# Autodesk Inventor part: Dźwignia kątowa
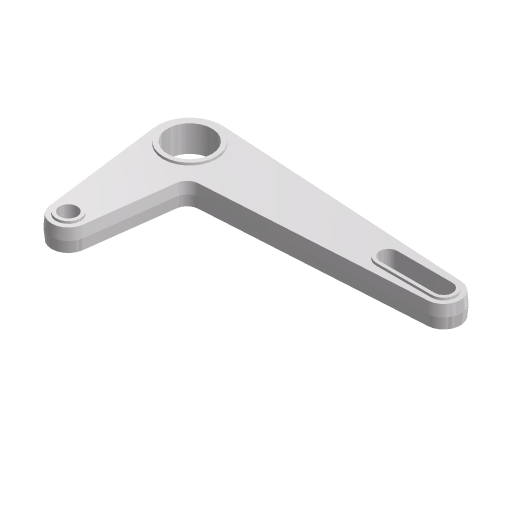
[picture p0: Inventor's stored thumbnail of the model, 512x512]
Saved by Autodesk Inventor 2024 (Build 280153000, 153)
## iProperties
Company: ATC
Shininess: 20.0
Angle Display Precision: 2
Document Length Units: 11269
Document Angle Units: 11279
Document Time Units: 11290
Document Mass Units: 11283
Document Length Units Precision: 3
Document Angle Units Precision: 2
Created: 2023-03
Part Number: Dźwignia kątowa
Material: Kurs-AJ
Document SubType Name: Modelowanie
Designer: Andrzej Jaskulski
Density: 1 g/cm^3
Stock Number: Dźwignia kątowa
Mass: 346.136 g
Surface Area: 128.086 cm^2
Volume: 34.6136 cm^3
Appearance: Kurs-AJ
Checked By: A.J.
Engr Approved By: Andrzej Jaskulski
Mfg Approved By: Andrzej Jaskulski
Authority: A.J.
Density: 0.0
Volumn: 0.0
Area: 0.0
PropertySet Name: Model Information
Control State: 0
Master: False
Checked Out: False
Title: A.J.: Kurs R2024-MEP
Author: Andrzej Jaskulski
Revision Number: 1/24
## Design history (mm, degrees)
node "Bryła1"
node "Korpusy bryłowe"
node "Korpusy powierzchniowe"
node "Początek"
sketch "Szkic1"
  geometry: L1 (-25.035, -9.169)-(89.965, -9.169); L2 (-24.122, 5.803)-(90.452, -1.184); L3 (90.452, -17.155)-(-7.608, -23.135); L4 (-25.035, -9.169)-(-25.035, -66.201); L5 (-39.913, -11.079)-(-32.97, -65.188); L6 (-17.1, -65.188)-(-12.263, -27.489); L7 (64.965, -5.169)-(89.965, -5.169); L8 (89.965, -13.169)-(64.965, -13.169); L9 (89.965, -3.169)-(64.965, -3.169); L10 (64.965, -15.169)-(89.965, -15.169); C1 r 12.5 at (-25.035, -9.169); C2 r 6 at (-25.035, -64.169); C3 r 4 at (-25.035, -64.169); C4 r 10 at (-25.035, -9.169); A1 r 8 centre (89.965, -9.169) between (90.452, -17.155) and (90.452, -1.184); A2 r 8 centre (-25.035, -64.169) between (-32.97, -65.188) and (-17.1, -65.188); A3 r 4 centre (64.965, -9.169) between (64.965, -5.169) and (64.965, -13.169); A4 r 4 centre (89.965, -9.169) between (89.965, -13.169) and (89.965, -5.169); A5 r 113.425 centre (-25.035, -9.169) between (67.111, -75.309) and (85.385, 16.766); A6 r 5 centre (-7.304, -28.125) between (-7.608, -23.135) and (-12.263, -27.489); A7 r 15 centre (-25.035, -9.169) between (-24.122, 5.803) and (-39.913, -11.079); A8 r 6 centre (64.965, -9.169) between (64.965, -3.169) and (64.965, -15.169); A9 r 6 centre (89.965, -9.169) between (89.965, -15.169) and (89.965, -3.169)
  constraints: 20 end point, 18 point on circle, 13 centre point, 11 tangent, 6 coincident, 2 horizontal, 2 parallel, 1 concentric, 1 perpendicular, 6 other
  dimensions: "d0" = 25 diameter of C1; "d3" = 8 radius of A2; "d4" = 8 radius of A1; "d5" = 55 distance of A2.centre L1.start; "d7" = 4 radius of A3; "d8" = 4 radius of A4 (= d7); "d9" = 115 distance of L1.start L1.end; "d10" = 25 distance of L1.end A3.centre; "d11" = 12 diameter of C2; "d12" = 8 diameter of C3; "d13" = 5 radius of A6; "d14" = 30 diameter of A7; "d15" = 20 diameter of C4; "d20" = 2 distance between parallel lines of L9 L7
extrude "Wyciągnięcie proste1" new body sketch "Szkic1" stored distance "d16" = 10; taper "d17" = -5 deg
extrude "Wyciągnięcie proste2" join sketch "Szkic1" stored distance "d18" = 12; taper "d19" = -5 deg
extrude "Wyciągnięcie proste3" cut sketch "Szkic1" extent not by distance; stored distance "d21" = 16; taper "d22" = 0 deg
node "Płaszczyzna konstrukcyjna1"
node "Płaszczyzna YZ"
node "Płaszczyzna XZ"
node "Płaszczyzna XY"
node "Oś X"
node "Oś Y"
node "Oś Z"
node "Punkt środkowy"
